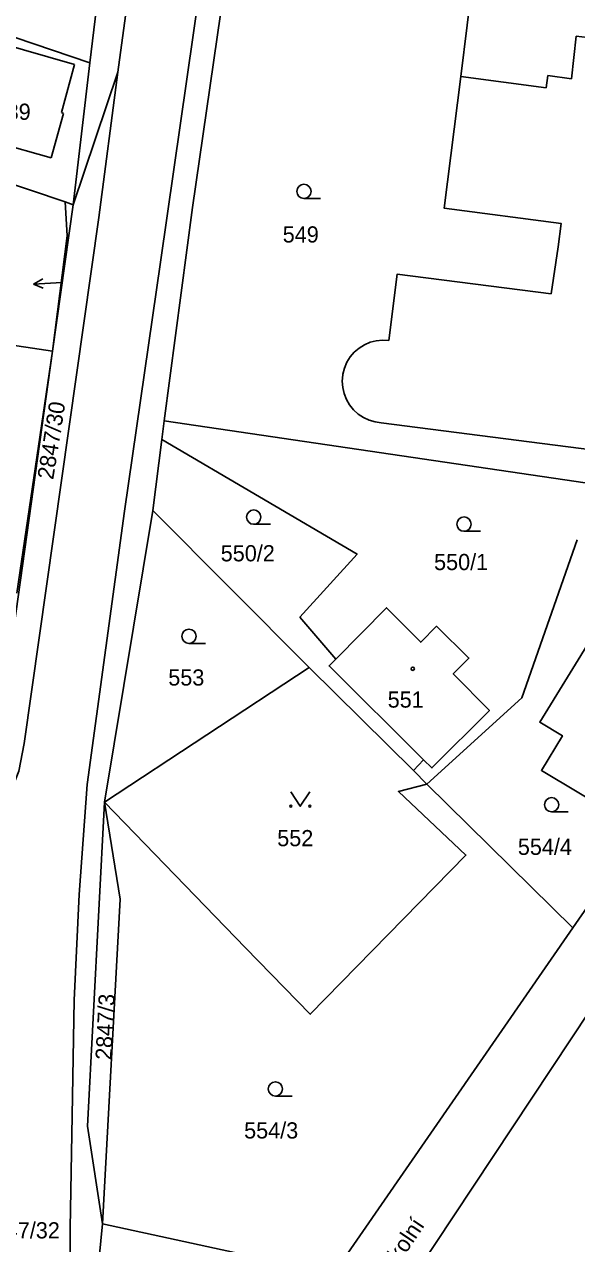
# Model space of a CAD drawing. Extents: x -558500 to -557517, y -1073973 to -1073051.
# Drawn here: x -558184.3 to -558126.2, y -1073668.6 to -1073540.5 of the extents above; entities that cross this region are included whole.
import ezdxf

# ---------------------------------------------------------------- set-up
doc = ezdxf.new("R2010")
doc.units = 0
for name, color, linetype in [('Hranice parcel', 7, 'Continuous'), ('Parcelní čísla', 7, 'Continuous'), ('Pop  PČ popisy', 7, 'Continuous'), ('Vnitřní kresba', 7, 'Continuous'), ('Značky budov', 7, 'Continuous'), ('Značky kultur', 7, 'Continuous')]:
    doc.layers.add(name, color=color, linetype=linetype)

msp = doc.modelspace()

# ---------------------------------------------------------------- linework, layer by layer
at = {"layer": 'Hranice parcel'}
for p, q in [((-558177.37, -1073544.49), (-558173.92, -1073515.47)), ((-558179.14, -1073559.41), (-558177.37, -1073544.49)), ((-558179.14, -1073559.41), (-558174.43, -1073545.49)), ((-558174.43, -1073545.49), (-558176.44, -1073560.75)), ((-558210.55, -1073548.74), (-558179.99, -1073559.12)), ((-558181.3, -1073574.78), (-558179.14, -1073559.41)), ((-558179.99, -1073559.12), (-558179.14, -1073559.41)), ((-558219.67, -1073569.09), (-558181.3, -1073574.78)), ((-558187.72, -1073620.52), (-558181.3, -1073574.78)), ((-558185.06, -1073600.21), (-558181.3, -1073574.78)), ((-558169.56, -1073582.12), (-558169.81, -1073584.08)), ((-558169.56, -1073582.12), (-558124.1, -1073588.8)), ((-558146.72, -1073582.31), (-558116.26, -1073586.22)), ((-558169.81, -1073584.08), (-558170.74, -1073591.52)), ((-558175.82, -1073622.18), (-558170.74, -1073591.52)), ((-558154.32, -1073608.02), (-558170.74, -1073591.52)), ((-558155.28, -1073602.76), (-558151.5, -1073607.15)), ((-558154.32, -1073608.02), (-558175.82, -1073622.18)), ((-558143.35, -1073618.87), (-558154.32, -1073608.02)), ((-558142.28, -1073617.72), (-558143.35, -1073618.87)), ((-558141.92, -1073620.28), (-558143.35, -1073618.87)), ((-558126.57, -1073635.37), (-558141.92, -1073620.28)), ((-558119.53, -1073625.2), (-558126.57, -1073635.37)), ((-558126.57, -1073635.37), (-558152.59, -1073672.96)), ((-558176.83, -1073674.75), (-558176.05, -1073666.5))]:
    msp.add_line(p, q, dxfattribs=at)
for points in [[(-558086.19, -1073392.25), (-558100.56, -1073410.01), (-558117.51, -1073431.08), (-558131.78, -1073449.27), (-558138.48, -1073457.68), (-558143.38, -1073464.02), (-558146.99, -1073468.89), (-558150.46, -1073473.83), (-558152.02, -1073476.41), (-558154.26, -1073480.97), (-558156.46, -1073486.6), (-558158.91, -1073494.31), (-558160.3, -1073500.48), (-558162.16, -1073510.4), (-558165.76, -1073536.46), (-558169.94, -1073565.43), (-558173.74, -1073591.61), (-558177.66, -1073620.33), (-558178.51, -1073631.87), (-558179.02, -1073643), (-558179.24, -1073655.12), (-558179.45, -1073666.94), (-558179.49, -1073675.4)], [(-558165.84, -1073492.01), (-558171, -1073520.22), (-558174.43, -1073545.49)], [(-558169.56, -1073582.12), (-558166.59, -1073559.69), (-558162.5, -1073531.6)], [(-558203.93, -1073535.45), (-558199.11, -1073537.11), (-558193.35, -1073539.1), (-558189.69, -1073540.36), (-558187.24, -1073541.19), (-558177.37, -1073544.49)], [(-558137.04, -1073535.13), (-558138.34, -1073545.94), (-558140.1, -1073559.78), (-558127.81, -1073561.38), (-558128.13, -1073563.82), (-558128.85, -1073568.77)], [(-558181.3, -1073574.78), (-558179.75, -1073562.68), (-558179.99, -1073559.12)], [(-558176.44, -1073560.75), (-558184.28, -1073616.01), (-558184.84, -1073618.94), (-558185.24, -1073619.89), (-558185.86, -1073620.72), (-558186.64, -1073621.38)], [(-558128.85, -1073568.77), (-558145.05, -1073566.7), (-558145.94, -1073573.66)], [(-558145.94, -1073573.66), (-558146.6, -1073573.63), (-558147.25, -1073573.7), (-558147.89, -1073573.86), (-558148.5, -1073574.12), (-558149.06, -1073574.47), (-558149.56, -1073574.9), (-558149.98, -1073575.4), (-558150.33, -1073575.96), (-558150.59, -1073576.57), (-558150.76, -1073577.21), (-558150.78, -1073577.3), (-558150.83, -1073577.96), (-558150.78, -1073578.62), (-558150.63, -1073579.26), (-558150.39, -1073579.87), (-558150.06, -1073580.44), (-558149.64, -1073580.95), (-558149.15, -1073581.4), (-558148.6, -1073581.76), (-558148.01, -1073582.04), (-558147.37, -1073582.22), (-558146.72, -1073582.31)], [(-558169.81, -1073584.08), (-558149.27, -1073596.11), (-558155.28, -1073602.76)], [(-558126.13, -1073594.62), (-558131.94, -1073611.23), (-558141.92, -1073620.28)], [(-558142.28, -1073617.72), (-558141.4, -1073618.59), (-558135.35, -1073612.55), (-558139.15, -1073608.7), (-558137.51, -1073607.05), (-558140.91, -1073603.7), (-558142.57, -1073605.38), (-558146.16, -1073601.75), (-558151.5, -1073607.15)], [(-558117.76, -1073617.53), (-558119.58, -1073620.56), (-558120.26, -1073620.18), (-558122.2, -1073623.43), (-558129.88, -1073618.85), (-558127.67, -1073615.2), (-558130.05, -1073613.78), (-558124.22, -1073604.32), (-558119.25, -1073607.46), (-558119.52, -1073607.94), (-558118.12, -1073608.84), (-558117.4, -1073607.72), (-558115.73, -1073608.72)], [(-558151.5, -1073607.15), (-558152.22, -1073607.87), (-558142.28, -1073617.72)], [(-558175.82, -1073622.18), (-558161, -1073637.48), (-558154.2, -1073644.46), (-558137.82, -1073627.75), (-558144.92, -1073621.06), (-558141.92, -1073620.28)], [(-558175.82, -1073622.18), (-558177.63, -1073656.22), (-558176.05, -1073666.5)], [(-558175.82, -1073622.18), (-558174.18, -1073632.38), (-558176.05, -1073666.5)], [(-558143.16, -1073671.79), (-558122.68, -1073640.91), (-558116.74, -1073631.82), (-558110.18, -1073623.69)], [(-558176.05, -1073666.5), (-558158.95, -1073670.2), (-558152.59, -1073672.96)]]:
    msp.add_lwpolyline(points, dxfattribs=at)
at = {"layer": 'Pop  PČ popisy'}
for p, q in [((-558183.31, -1073567.74), (-558182.33, -1073567.19)), ((-558180.31, -1073567.58), (-558183.31, -1073567.74)), ((-558183.31, -1073567.74), (-558182.28, -1073568.19))]:
    msp.add_line(p, q, dxfattribs=at)
at = {"layer": 'Vnitřní kresba'}
for p, q in [((-558126.72, -1073546.2), (-558126.22, -1073541.7)), ((-558126.22, -1073541.7), (-558120.27, -1073542.43)), ((-558187.49, -1073542.24), (-558179, -1073544.67)), ((-558180.35, -1073549.71), (-558179, -1073544.67)), ((-558138.34, -1073545.94), (-558129.39, -1073547.14)), ((-558129.39, -1073547.14), (-558129.22, -1073545.83)), ((-558129.22, -1073545.83), (-558126.72, -1073546.2)), ((-558181.43, -1073554.48), (-558180.14, -1073549.84)), ((-558180.35, -1073549.71), (-558180.14, -1073549.84)), ((-558189.68, -1073552.16), (-558181.43, -1073554.48))]:
    msp.add_line(p, q, dxfattribs=at)
at = {"layer": 'Značky budov'}
msp.add_circle((-558143.42, -1073608.17), 0.175, dxfattribs=at)
at = {"layer": 'Značky kultur'}
for p, q in [((-558154.86, -1073558.76), (-558153.11, -1073558.76)), ((-558160.14, -1073592.98), (-558158.39, -1073592.98)), ((-558138.02, -1073593.72), (-558136.27, -1073593.72)), ((-558166.95, -1073605.5), (-558165.2, -1073605.5)), ((-558128.81, -1073623.2), (-558127.06, -1073623.2)), ((-558157.86, -1073653.06), (-558156.11, -1073653.06))]:
    msp.add_line(p, q, dxfattribs=at)
msp.add_lwpolyline([(-558156.24, -1073621.11), (-558155.24, -1073622.61), (-558154.24, -1073621.11)], dxfattribs=at)
for centre, radius in [((-558154.86, -1073558.01), 0.75), ((-558160.14, -1073592.23), 0.75), ((-558138.02, -1073592.97), 0.75), ((-558166.95, -1073604.75), 0.75), ((-558156.24, -1073622.61), 0.1), ((-558154.24, -1073622.61), 0.1), ((-558128.81, -1073622.45), 0.75), ((-558157.86, -1073652.31), 0.75)]:
    msp.add_circle(centre, radius, dxfattribs=at)

# ---------------------------------------------------------------- texts
at = {"layer": 'Parcelní čísla'}
for s, p in [('539', (-558187.39, -1073550.49)), ('549', (-558157.09, -1073563.38)), ('550/2', (-558163.61, -1073596.88)), ('550/1', (-558141.17, -1073597.8)), ('553', (-558169.13, -1073609.93)), ('551', (-558146.05, -1073612.25)), ('552', (-558157.67, -1073626.81)), ('554/4', (-558132.36, -1073627.72)), ('554/3', (-558161.15, -1073657.52)), ('2847/32', (-558188.75, -1073668.02))]:
    msp.add_text(s, height=1.7, dxfattribs=at).set_placement(p)
for s, rotation, p in [('2847/30', 81, (-558181.23, -1073588.36)), ('2847/3', 87, (-558175.1, -1073649.31))]:
    msp.add_text(s, height=1.7, rotation=rotation, dxfattribs=at).set_placement(p)
at = {"layer": 'Pop  PČ popisy'}
msp.add_text('Školní', height=1.7, rotation=56, dxfattribs=at).set_placement((-558145.62, -1073671.85))

doc.saveas('drawing.dxf')
